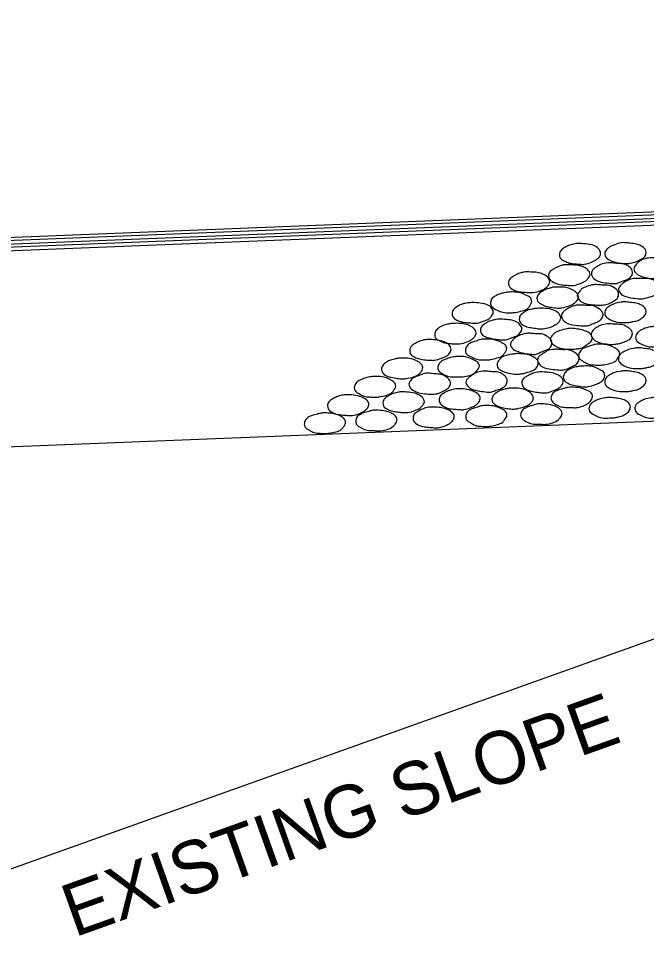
# Model space of a CAD drawing. Extents: x 714919 to 718439, y 1619644 to 1621844.
# Drawn here: x 716119 to 716262.2, y 1620757.6 to 1620966.5 of the extents above; entities that cross this region are included whole.
import ezdxf

# ---------------------------------------------------------------- set-up
doc = ezdxf.new("R2010")
doc.units = 0
doc.layers.add('R_Annotation', color=7, linetype='Continuous')
doc.layers.add('R_Draft', color=7, linetype='Continuous')

msp = doc.modelspace()

# ---------------------------------------------------------------- linework, layer by layer
at = {"layer": 'R_Draft'}
for p, q in [((716083.88, 1620915.32), (717366.08, 1620966.55)), ((716079.01, 1620912.92), (717370.38, 1620964.41)), ((716080.68, 1620913.71), (717368.96, 1620965.14)), ((716082.38, 1620914.6), (717367.45, 1620965.87)), ((716077.33, 1620912.05), (717371.84, 1620963.68)), ((715980.19, 1620863.5), (716482.51, 1620883.51)), ((716371.46, 1620863.61), (716076.17, 1620758.09))]:
    msp.add_line(p, q, dxfattribs=at)
for points in [[(716247.01, 1620915.27), (716248.65, 1620915.12), (716250.6, 1620914.57), (716251.52, 1620913.6), (716251.69, 1620913.07), (716251.23, 1620912.03), (716250.75, 1620911.63), (716249.63, 1620911.05), (716248.01, 1620910.53), (716247.16, 1620910.53), (716245.89, 1620910.64), (716244.55, 1620910.82), (716243.47, 1620911.26), (716242.43, 1620912.08), (716242.3, 1620912.76), (716242.59, 1620913.62), (716243.36, 1620914.28), (716244.13, 1620914.68), (716245.23, 1620915.07), (716245.89, 1620915.2), (716247.01, 1620915.27)], [(716257.38, 1620910.71), (716255.71, 1620910.83), (716253.81, 1620911.48), (716252.74, 1620912.37), (716252.62, 1620913), (716253.13, 1620913.97), (716253.69, 1620914.46), (716254.84, 1620914.93), (716256.39, 1620915.45), (716257.17, 1620915.45), (716258.46, 1620915.32), (716259.87, 1620915.12), (716260.89, 1620914.75), (716261.89, 1620913.88), (716262.07, 1620913.28), (716261.78, 1620912.34), (716261.02, 1620911.76), (716260.26, 1620911.35), (716259.14, 1620910.92), (716258.46, 1620910.77), (716257.38, 1620910.71)], [(716244.47, 1620910.43), (716246.12, 1620910.32), (716248.19, 1620909.72), (716249.13, 1620908.78), (716249.29, 1620908.21), (716248.73, 1620907.19), (716248.31, 1620906.76), (716247.09, 1620906.19), (716245.59, 1620905.72), (716244.7, 1620905.72), (716243.44, 1620905.79), (716242.06, 1620905.98), (716241.03, 1620906.4), (716239.97, 1620907.28), (716239.83, 1620907.91), (716240.14, 1620908.83), (716240.9, 1620909.41), (716241.66, 1620909.83), (716242.74, 1620910.25), (716243.44, 1620910.4), (716244.47, 1620910.43)], [(716254.27, 1620906.14), (716252.64, 1620906.34), (716250.7, 1620906.89), (716249.76, 1620907.81), (716249.58, 1620908.39), (716250.02, 1620909.38), (716250.63, 1620909.86), (716251.69, 1620910.45), (716253.32, 1620910.87), (716254.1, 1620910.87), (716255.39, 1620910.74), (716256.8, 1620910.64), (716257.87, 1620910.22), (716258.8, 1620909.31), (716258.97, 1620908.73), (716258.66, 1620907.79), (716257.96, 1620907.19), (716257.14, 1620906.86), (716256.04, 1620906.43), (716255.39, 1620906.19), (716254.27, 1620906.14)], [(716264.01, 1620907.28), (716262.35, 1620907.42), (716260.37, 1620908.07), (716259.44, 1620908.91), (716259.26, 1620909.51), (716259.81, 1620910.5), (716260.32, 1620911.05), (716261.39, 1620911.68), (716263.01, 1620911.98), (716263.77, 1620911.98), (716265.02, 1620912.03), (716266.44, 1620911.81), (716267.56, 1620911.32), (716268.54, 1620910.45), (716268.7, 1620909.9), (716268.38, 1620908.86), (716267.64, 1620908.29), (716266.86, 1620907.97), (716265.76, 1620907.58), (716265.02, 1620907.36), (716264.01, 1620907.28)], [(716235.35, 1620908.78), (716237, 1620908.7), (716239.02, 1620908.07), (716239.96, 1620907.11), (716240.1, 1620906.56), (716239.62, 1620905.54), (716239.08, 1620905.06), (716237.92, 1620904.49), (716236.35, 1620904.09), (716235.54, 1620904.09), (716234.28, 1620904.19), (716232.87, 1620904.33), (716231.85, 1620904.72), (716230.83, 1620905.63), (716230.7, 1620906.24), (716231.01, 1620907.16), (716231.74, 1620907.76), (716232.5, 1620908.17), (716233.55, 1620908.6), (716234.28, 1620908.76), (716235.35, 1620908.78)], [(716251.2, 1620901.24), (716249.49, 1620901.34), (716247.5, 1620901.89), (716246.54, 1620902.89), (716246.38, 1620903.43), (716246.98, 1620904.4), (716247.4, 1620904.91), (716248.53, 1620905.46), (716250.08, 1620905.88), (716251.02, 1620905.88), (716252.25, 1620905.79), (716253.61, 1620905.69), (716254.66, 1620905.29), (716255.63, 1620904.35), (716255.8, 1620903.77), (716255.52, 1620902.84), (716254.79, 1620902.24), (716254.03, 1620901.78), (716252.85, 1620901.39), (716252.25, 1620901.27), (716251.2, 1620901.24)], [(716260.71, 1620902.63), (716259, 1620902.84), (716256.99, 1620903.36), (716255.94, 1620904.3), (716255.8, 1620904.85), (716256.39, 1620905.84), (716256.91, 1620906.31), (716258.16, 1620907), (716259.68, 1620907.32), (716260.47, 1620907.32), (716261.73, 1620907.29), (716263.12, 1620907.16), (716264.19, 1620906.69), (716265.08, 1620905.77), (716265.24, 1620905.19), (716264.94, 1620904.3), (716264.22, 1620903.67), (716263.5, 1620903.28), (716262.44, 1620902.96), (716261.78, 1620902.78), (716260.71, 1620902.63)], [(716231.22, 1620904.23), (716232.87, 1620904.12), (716234.83, 1620903.43), (716235.88, 1620902.6), (716235.99, 1620902.07), (716235.48, 1620900.95), (716234.98, 1620900.38), (716233.83, 1620899.92), (716232.29, 1620899.58), (716231.43, 1620899.48), (716230.19, 1620899.51), (716228.73, 1620899.8), (716227.76, 1620900.27), (716226.73, 1620901.05), (716226.58, 1620901.66), (716226.85, 1620902.6), (716227.62, 1620903.25), (716228.36, 1620903.62), (716229.48, 1620903.99), (716230.17, 1620904.12), (716231.22, 1620904.23)], [(716241.92, 1620905.32), (716243.6, 1620905.29), (716245.57, 1620904.53), (716246.48, 1620903.73), (716246.66, 1620903.09), (716246.12, 1620902.03), (716245.62, 1620901.6), (716244.54, 1620901.08), (716242.89, 1620900.63), (716242.09, 1620900.53), (716240.83, 1620900.69), (716239.49, 1620900.9), (716238.39, 1620901.34), (716237.34, 1620902.12), (716237.19, 1620902.78), (716237.5, 1620903.67), (716238.31, 1620904.32), (716239.04, 1620904.75), (716240.14, 1620905.09), (716240.83, 1620905.29), (716241.92, 1620905.32)], [(716222.54, 1620901.81), (716224.22, 1620901.69), (716226.14, 1620901.14), (716227.11, 1620900.19), (716227.23, 1620899.61), (716226.76, 1620898.61), (716226.27, 1620898.14), (716225.14, 1620897.65), (716223.54, 1620897.12), (716222.71, 1620897.12), (716221.47, 1620897.23), (716220.09, 1620897.41), (716219.01, 1620897.75), (716217.97, 1620898.69), (716217.84, 1620899.28), (716218.15, 1620900.22), (716218.9, 1620900.81), (716219.67, 1620901.27), (716220.79, 1620901.63), (716221.47, 1620901.74), (716222.54, 1620901.81)], [(716257.32, 1620897.29), (716255.63, 1620897.33), (716253.81, 1620897.97), (716252.74, 1620898.88), (716252.62, 1620899.4), (716253.06, 1620900.51), (716253.69, 1620900.98), (716254.76, 1620901.52), (716256.39, 1620901.89), (716257.17, 1620901.97), (716258.45, 1620901.86), (716259.82, 1620901.65), (716260.89, 1620901.27), (716261.89, 1620900.42), (716262.07, 1620899.85), (716261.78, 1620898.91), (716261.02, 1620898.23), (716260.26, 1620897.76), (716259.11, 1620897.49), (716258.38, 1620897.33), (716257.32, 1620897.29)], [(716237.82, 1620900.51), (716239.54, 1620900.45), (716241.45, 1620899.85), (716242.43, 1620898.96), (716242.59, 1620898.38), (716242.11, 1620897.29), (716241.56, 1620896.86), (716240.49, 1620896.31), (716238.83, 1620895.89), (716238.02, 1620895.81), (716236.82, 1620895.95), (716235.46, 1620896.16), (716234.34, 1620896.53), (716233.29, 1620897.39), (716233.16, 1620897.97), (716233.44, 1620898.91), (716234.22, 1620899.58), (716234.94, 1620900.03), (716236.06, 1620900.32), (716236.85, 1620900.45), (716237.82, 1620900.51)], [(716247.61, 1620896.49), (716245.88, 1620896.66), (716243.94, 1620897.2), (716242.92, 1620898.17), (716242.76, 1620898.73), (716243.29, 1620899.8), (716243.84, 1620900.22), (716244.96, 1620900.81), (716246.57, 1620901.24), (716247.37, 1620901.24), (716248.61, 1620901.14), (716249.99, 1620901.05), (716251.14, 1620900.51), (716252.07, 1620899.71), (716252.25, 1620899.04), (716251.91, 1620898.1), (716251.2, 1620897.54), (716250.39, 1620897.17), (716249.36, 1620896.76), (716248.61, 1620896.52), (716247.61, 1620896.49)], [(716228.93, 1620898.02), (716230.64, 1620897.91), (716232.63, 1620897.36), (716233.58, 1620896.37), (716233.76, 1620895.82), (716233.23, 1620894.8), (716232.74, 1620894.33), (716231.56, 1620893.83), (716229.99, 1620893.33), (716229.2, 1620893.33), (716227.92, 1620893.44), (716226.53, 1620893.7), (716225.51, 1620893.98), (716224.44, 1620894.88), (716224.3, 1620895.52), (716224.61, 1620896.4), (716225.4, 1620897.02), (716226.14, 1620897.47), (716227.21, 1620897.81), (716227.92, 1620897.99), (716228.93, 1620898.02)], [(716218.59, 1620897.08), (716220.27, 1620897.02), (716222.23, 1620896.36), (716223.17, 1620895.48), (716223.33, 1620894.95), (716222.84, 1620893.85), (716222.31, 1620893.4), (716221.23, 1620892.85), (716219.61, 1620892.44), (716218.75, 1620892.39), (716217.54, 1620892.46), (716216.19, 1620892.67), (716215.08, 1620893.09), (716214.03, 1620893.88), (716213.88, 1620894.54), (716214.17, 1620895.42), (716215, 1620896.15), (716215.69, 1620896.53), (716216.83, 1620896.89), (716217.57, 1620897.02), (716218.59, 1620897.08)], [(716245.02, 1620891.21), (716243.37, 1620891.24), (716241.37, 1620891.94), (716240.39, 1620892.86), (716240.23, 1620893.44), (716240.8, 1620894.48), (716241.32, 1620894.95), (716242.43, 1620895.42), (716244.07, 1620895.85), (716244.88, 1620895.95), (716246.12, 1620895.82), (716247.46, 1620895.58), (716248.53, 1620895.19), (716249.58, 1620894.4), (716249.76, 1620893.78), (716249.41, 1620892.83), (716248.61, 1620892.28), (716247.9, 1620891.73), (716246.85, 1620891.37), (716246.11, 1620891.24), (716245.02, 1620891.21)], [(716254.19, 1620892.26), (716252.61, 1620892.43), (716250.67, 1620892.99), (716249.73, 1620893.87), (716249.55, 1620894.46), (716249.94, 1620895.42), (716250.54, 1620896), (716251.57, 1620896.57), (716253.26, 1620896.94), (716254.06, 1620896.94), (716255.37, 1620896.89), (716256.75, 1620896.73), (716257.8, 1620896.24), (716258.77, 1620895.37), (716258.93, 1620894.74), (716258.64, 1620893.85), (716257.93, 1620893.22), (716257.11, 1620892.86), (716255.97, 1620892.52), (716255.34, 1620892.38), (716254.19, 1620892.26)], [(716264.35, 1620891.73), (716262.67, 1620891.76), (716260.84, 1620892.41), (716259.77, 1620893.32), (716259.66, 1620893.83), (716260.1, 1620894.95), (716260.73, 1620895.42), (716261.8, 1620895.95), (716263.43, 1620896.32), (716264.21, 1620896.41), (716265.49, 1620896.29), (716266.86, 1620896.08), (716267.93, 1620895.71), (716268.93, 1620894.85), (716269.11, 1620894.29), (716268.82, 1620893.35), (716268.06, 1620892.67), (716267.3, 1620892.2), (716266.15, 1620891.92), (716265.42, 1620891.76), (716264.35, 1620891.73)], [(716212.81, 1620893.4), (716214.46, 1620893.28), (716216.5, 1620892.64), (716217.49, 1620891.7), (716217.63, 1620891.16), (716217.08, 1620890.08), (716216.63, 1620889.69), (716215.4, 1620889.17), (716213.86, 1620888.67), (716213.04, 1620888.67), (716211.76, 1620888.74), (716210.4, 1620888.98), (716209.35, 1620889.37), (716208.33, 1620890.18), (716208.19, 1620890.89), (716208.48, 1620891.76), (716209.24, 1620892.41), (716210, 1620892.77), (716211.07, 1620893.19), (716211.76, 1620893.36), (716212.81, 1620893.4)], [(716225.54, 1620893.51), (716227.19, 1620893.4), (716229.2, 1620892.67), (716230.17, 1620891.88), (716230.3, 1620891.33), (716229.75, 1620890.21), (716229.35, 1620889.72), (716228.13, 1620889.19), (716226.61, 1620888.82), (716225.71, 1620888.74), (716224.48, 1620888.77), (716223.04, 1620889.04), (716222.05, 1620889.56), (716221.01, 1620890.29), (716220.9, 1620890.99), (716221.19, 1620891.88), (716221.9, 1620892.52), (716222.7, 1620892.86), (716223.8, 1620893.22), (716224.44, 1620893.4), (716225.54, 1620893.51)], [(716236.03, 1620890.05), (716234.39, 1620890.23), (716232.39, 1620890.84), (716231.3, 1620891.73), (716231.16, 1620892.36), (716231.69, 1620893.33), (716232.26, 1620893.83), (716233.41, 1620894.43), (716234.94, 1620894.8), (716235.82, 1620894.8), (716237.05, 1620894.69), (716238.49, 1620894.61), (716239.51, 1620894.08), (716240.46, 1620893.25), (716240.61, 1620892.59), (716240.3, 1620891.67), (716239.59, 1620891.12), (716238.86, 1620890.81), (716237.73, 1620890.39), (716237.08, 1620890.06), (716236.03, 1620890.05)], [(716251.3, 1620892.34), (716252.9, 1620892.23), (716254.99, 1620891.45), (716255.91, 1620890.69), (716256.05, 1620890.08), (716255.52, 1620889.04), (716255.13, 1620888.49), (716253.93, 1620887.98), (716252.4, 1620887.65), (716251.46, 1620887.57), (716250.23, 1620887.6), (716248.79, 1620887.82), (716247.82, 1620888.35), (716246.82, 1620889.13), (716246.66, 1620889.77), (716247.01, 1620890.69), (716247.67, 1620891.33), (716248.45, 1620891.65), (716249.6, 1620892.04), (716250.2, 1620892.23), (716251.3, 1620892.34)], [(716260.43, 1620886.82), (716258.74, 1620886.85), (716256.91, 1620887.5), (716255.85, 1620888.41), (716255.73, 1620888.92), (716256.17, 1620890.04), (716256.8, 1620890.51), (716257.87, 1620891.04), (716259.5, 1620891.42), (716260.28, 1620891.5), (716261.56, 1620891.38), (716262.93, 1620891.17), (716264, 1620890.8), (716265, 1620889.94), (716265.18, 1620889.38), (716264.89, 1620888.44), (716264.13, 1620887.76), (716263.37, 1620887.29), (716262.22, 1620887.02), (716261.49, 1620886.85), (716260.43, 1620886.82)], [(716206.46, 1620889.16), (716208.11, 1620889.11), (716210.05, 1620888.41), (716211.02, 1620887.54), (716211.16, 1620886.99), (716210.69, 1620885.91), (716210.16, 1620885.42), (716209.08, 1620884.9), (716207.46, 1620884.51), (716206.59, 1620884.43), (716205.36, 1620884.53), (716204, 1620884.79), (716202.91, 1620885.11), (716201.93, 1620885.97), (716201.76, 1620886.57), (716202.07, 1620887.48), (716202.8, 1620888.19), (716203.56, 1620888.59), (716204.71, 1620888.92), (716205.39, 1620889.11), (716206.46, 1620889.16)], [(716219.22, 1620889.56), (716220.93, 1620889.45), (716222.89, 1620888.72), (716223.89, 1620887.91), (716224.06, 1620887.41), (716223.47, 1620886.29), (716223.02, 1620885.78), (716221.79, 1620885.21), (716220.27, 1620884.9), (716219.48, 1620884.87), (716218.22, 1620884.87), (716216.78, 1620885.06), (716215.74, 1620885.58), (716214.74, 1620886.36), (716214.59, 1620887.04), (716214.93, 1620887.91), (716215.63, 1620888.59), (716216.42, 1620888.92), (716217.5, 1620889.3), (716218.18, 1620889.45), (716219.22, 1620889.56)], [(716232.87, 1620885.49), (716231.19, 1620885.62), (716229.2, 1620886.29), (716228.18, 1620887.1), (716228.1, 1620887.65), (716228.55, 1620888.72), (716229.09, 1620889.27), (716230.22, 1620889.79), (716231.79, 1620890.08), (716232.63, 1620890.18), (716233.88, 1620890.11), (716235.32, 1620889.93), (716236.29, 1620889.48), (716237.31, 1620888.66), (716237.48, 1620888.04), (716237.16, 1620887.1), (716236.4, 1620886.42), (716235.69, 1620886.12), (716234.59, 1620885.78), (716233.92, 1620885.62), (716232.87, 1620885.49)], [(716242.13, 1620886.46), (716240.46, 1620886.63), (716238.47, 1620887.17), (716237.47, 1620888.14), (716237.29, 1620888.67), (716237.81, 1620889.72), (716238.44, 1620890.11), (716239.51, 1620890.81), (716241.14, 1620891.16), (716241.98, 1620891.16), (716243.19, 1620891.08), (716244.55, 1620891.02), (716245.65, 1620890.5), (716246.61, 1620889.68), (716246.77, 1620888.98), (716246.43, 1620888.07), (716245.67, 1620887.46), (716244.96, 1620887.14), (716243.87, 1620886.63), (716243.16, 1620886.47), (716242.13, 1620886.46)], [(716247.9, 1620887.36), (716249.6, 1620887.3), (716251.43, 1620886.6), (716252.53, 1620885.78), (716252.62, 1620885.15), (716252.17, 1620884.09), (716251.54, 1620883.63), (716250.51, 1620883.12), (716248.84, 1620882.69), (716248.08, 1620882.59), (716246.85, 1620882.74), (716245.51, 1620882.99), (716244.34, 1620883.38), (716243.36, 1620884.18), (716243.19, 1620884.84), (716243.5, 1620885.71), (716244.23, 1620886.39), (716244.99, 1620886.81), (716246.12, 1620887.14), (716246.88, 1620887.3), (716247.9, 1620887.36)], [(716212.86, 1620880.96), (716211.2, 1620881.07), (716209.21, 1620881.68), (716208.15, 1620882.62), (716208.01, 1620883.2), (716208.53, 1620884.24), (716209.09, 1620884.69), (716210.31, 1620885.18), (716211.91, 1620885.7), (716212.7, 1620885.7), (716213.96, 1620885.58), (716215.34, 1620885.42), (716216.36, 1620884.98), (716217.28, 1620884.14), (716217.47, 1620883.5), (716217.15, 1620882.56), (716216.47, 1620881.99), (716215.77, 1620881.64), (716214.69, 1620881.13), (716213.9, 1620880.99), (716212.86, 1620880.96)], [(716225.85, 1620881.44), (716224.19, 1620881.65), (716222.23, 1620882.17), (716221.18, 1620883.11), (716221, 1620883.64), (716221.55, 1620884.69), (716222.1, 1620885.08), (716223.25, 1620885.79), (716224.82, 1620886.18), (716225.67, 1620886.18), (716226.89, 1620886.07), (716228.31, 1620885.97), (716229.39, 1620885.49), (716230.27, 1620884.61), (716230.43, 1620883.96), (716230.14, 1620883.08), (716229.44, 1620882.43), (716228.7, 1620882.12), (716227.57, 1620881.73), (716226.94, 1620881.49), (716225.85, 1620881.44)], [(716238.39, 1620886), (716240.01, 1620885.91), (716242.06, 1620885.28), (716243.02, 1620884.35), (716243.16, 1620883.74), (716242.66, 1620882.74), (716242.13, 1620882.3), (716240.99, 1620881.76), (716239.42, 1620881.26), (716238.57, 1620881.26), (716237.29, 1620881.39), (716235.93, 1620881.62), (716234.86, 1620881.96), (716233.91, 1620882.83), (716233.73, 1620883.48), (716234.04, 1620884.4), (716234.75, 1620884.95), (716235.54, 1620885.36), (716236.64, 1620885.83), (716237.29, 1620885.97), (716238.39, 1620886)], [(716257.32, 1620881.58), (716255.63, 1620881.62), (716253.81, 1620882.26), (716252.74, 1620883.17), (716252.62, 1620883.69), (716253.06, 1620884.8), (716253.69, 1620885.27), (716254.76, 1620885.81), (716256.39, 1620886.18), (716257.17, 1620886.26), (716258.45, 1620886.15), (716259.82, 1620885.94), (716260.89, 1620885.56), (716261.89, 1620884.71), (716262.07, 1620884.14), (716261.78, 1620883.2), (716261.02, 1620882.52), (716260.26, 1620882.05), (716259.11, 1620881.78), (716258.38, 1620881.62), (716257.32, 1620881.58)], [(716200.23, 1620884.95), (716201.89, 1620884.9), (716203.85, 1620884.21), (716204.84, 1620883.38), (716205.02, 1620882.86), (716204.47, 1620881.73), (716203.98, 1620881.18), (716202.8, 1620880.68), (716201.26, 1620880.33), (716200.45, 1620880.28), (716199.18, 1620880.31), (716197.72, 1620880.52), (716196.73, 1620881.02), (716195.75, 1620881.8), (716195.57, 1620882.43), (716195.89, 1620883.38), (716196.62, 1620884.03), (716197.4, 1620884.4), (716198.5, 1620884.76), (716199.14, 1620884.9), (716200.23, 1620884.95)], [(716206.73, 1620881.46), (716208.38, 1620881.36), (716210.4, 1620880.75), (716211.37, 1620879.81), (716211.54, 1620879.23), (716210.99, 1620878.24), (716210.52, 1620877.75), (716209.35, 1620877.24), (716207.77, 1620876.77), (716206.96, 1620876.77), (716205.68, 1620876.86), (716204.32, 1620877.06), (716203.27, 1620877.43), (716202.22, 1620878.3), (716202.1, 1620878.93), (716202.4, 1620879.84), (716203.17, 1620880.44), (716203.9, 1620880.88), (716205.02, 1620881.26), (716205.68, 1620881.44), (716206.73, 1620881.46)], [(716219.54, 1620882.17), (716221.23, 1620882.04), (716223.1, 1620881.44), (716224.15, 1620880.49), (716224.25, 1620879.89), (716223.73, 1620878.92), (716223.25, 1620878.46), (716222.13, 1620877.93), (716220.53, 1620877.43), (716219.72, 1620877.43), (716218.43, 1620877.54), (716217.08, 1620877.69), (716216.02, 1620878.13), (716215.03, 1620878.98), (716214.87, 1620879.63), (716215.16, 1620880.52), (716215.89, 1620881.12), (716216.68, 1620881.59), (716217.8, 1620881.96), (716218.43, 1620882.12), (716219.54, 1620882.17)], [(716231.64, 1620882.3), (716233.29, 1620882.25), (716235.25, 1620881.59), (716236.19, 1620880.7), (716236.35, 1620880.13), (716235.9, 1620879.03), (716235.38, 1620878.58), (716234.28, 1620878.08), (716232.63, 1620877.64), (716231.79, 1620877.54), (716230.58, 1620877.67), (716229.23, 1620877.91), (716228.13, 1620878.32), (716227.08, 1620879.13), (716226.94, 1620879.78), (716227.23, 1620880.65), (716228.04, 1620881.33), (716228.73, 1620881.76), (716229.85, 1620882.09), (716230.61, 1620882.25), (716231.64, 1620882.3)], [(716245.12, 1620882.56), (716246.8, 1620882.38), (716248.65, 1620881.8), (716249.73, 1620880.94), (716249.83, 1620880.36), (716249.37, 1620879.35), (716248.76, 1620878.8), (716247.67, 1620878.24), (716246.11, 1620877.88), (716245.26, 1620877.88), (716244.02, 1620877.91), (716242.66, 1620878.08), (716241.56, 1620878.55), (716240.54, 1620879.44), (716240.38, 1620880.07), (716240.69, 1620880.96), (716241.41, 1620881.62), (716242.19, 1620881.91), (716243.32, 1620882.27), (716244.07, 1620882.46), (716245.12, 1620882.56)], [(716194.15, 1620880.81), (716195.88, 1620880.68), (716197.72, 1620880.07), (716198.76, 1620879.16), (716198.89, 1620878.55), (716198.34, 1620877.54), (716197.85, 1620877.11), (716196.73, 1620876.57), (716195.13, 1620876.09), (716194.36, 1620876.09), (716193.06, 1620876.18), (716191.7, 1620876.35), (716190.62, 1620876.77), (716189.6, 1620877.64), (716189.47, 1620878.3), (716189.75, 1620879.18), (716190.51, 1620879.78), (716191.27, 1620880.21), (716192.4, 1620880.62), (716193.06, 1620880.75), (716194.15, 1620880.81)], [(716238.26, 1620878.77), (716239.86, 1620878.61), (716241.77, 1620878.01), (716242.76, 1620877.14), (716242.92, 1620876.57), (716242.45, 1620875.54), (716241.92, 1620875), (716240.82, 1620874.44), (716239.2, 1620874.08), (716238.39, 1620874.08), (716237.11, 1620874.11), (716235.75, 1620874.24), (716234.65, 1620874.76), (716233.62, 1620875.6), (716233.47, 1620876.26), (716233.79, 1620877.19), (716234.54, 1620877.79), (716235.32, 1620878.13), (716236.4, 1620878.46), (716237.16, 1620878.69), (716238.26, 1620878.77)], [(716253.72, 1620875.53), (716252.03, 1620875.56), (716250.21, 1620876.21), (716249.14, 1620877.11), (716249.02, 1620877.63), (716249.46, 1620878.75), (716250.09, 1620879.22), (716251.16, 1620879.75), (716252.79, 1620880.12), (716253.57, 1620880.2), (716254.85, 1620880.09), (716256.22, 1620879.88), (716257.29, 1620879.51), (716258.29, 1620878.65), (716258.47, 1620878.08), (716258.18, 1620877.15), (716257.42, 1620876.47), (716256.66, 1620876), (716255.51, 1620875.72), (716254.78, 1620875.56), (716253.72, 1620875.53)], [(716264.19, 1620875.53), (716262.51, 1620875.56), (716260.68, 1620876.21), (716259.61, 1620877.11), (716259.5, 1620877.63), (716259.93, 1620878.75), (716260.57, 1620879.22), (716261.63, 1620879.75), (716263.27, 1620880.12), (716264.04, 1620880.2), (716265.32, 1620880.09), (716266.7, 1620879.88), (716267.76, 1620879.51), (716268.77, 1620878.65), (716268.95, 1620878.08), (716268.65, 1620877.15), (716267.89, 1620876.47), (716267.13, 1620876), (716265.98, 1620875.72), (716265.26, 1620875.56), (716264.19, 1620875.53)], [(716188.79, 1620876.7), (716190.49, 1620876.57), (716192.5, 1620875.91), (716193.43, 1620875.07), (716193.58, 1620874.55), (716193.06, 1620873.43), (716192.61, 1620872.9), (716191.38, 1620872.35), (716189.86, 1620872.06), (716189.05, 1620871.99), (716187.82, 1620872.03), (716186.38, 1620872.19), (716185.33, 1620872.74), (716184.31, 1620873.51), (716184.16, 1620874.15), (716184.46, 1620875.07), (716185.2, 1620875.75), (716185.94, 1620876.09), (716187.08, 1620876.41), (716187.79, 1620876.57), (716188.79, 1620876.7)], [(716200.6, 1620877.33), (716202.25, 1620877.15), (716204.19, 1620876.54), (716205.16, 1620875.67), (716205.31, 1620875.12), (716204.87, 1620874.08), (716204.34, 1620873.58), (716203.24, 1620872.96), (716201.6, 1620872.62), (716200.76, 1620872.62), (716199.52, 1620872.66), (716198.16, 1620872.8), (716197.07, 1620873.34), (716196.01, 1620874.15), (716195.89, 1620874.81), (716196.15, 1620875.73), (716196.96, 1620876.33), (716197.66, 1620876.67), (716198.85, 1620876.99), (716199.56, 1620877.24), (716200.6, 1620877.33)], [(716213.64, 1620878.01), (716215.3, 1620877.88), (716217.18, 1620877.28), (716218.22, 1620876.35), (716218.35, 1620875.76), (716217.84, 1620874.76), (716217.34, 1620874.31), (716216.26, 1620873.76), (716214.66, 1620873.3), (716213.78, 1620873.3), (716212.52, 1620873.42), (716211.16, 1620873.58), (716210.1, 1620873.97), (716209.08, 1620874.84), (716208.96, 1620875.46), (716209.21, 1620876.38), (716209.97, 1620876.96), (716210.74, 1620877.4), (716211.89, 1620877.82), (716212.52, 1620877.96), (716213.64, 1620878.01)], [(716225.59, 1620878.35), (716227.23, 1620878.27), (716229.27, 1620877.54), (716230.2, 1620876.75), (716230.35, 1620876.18), (716229.78, 1620875.08), (716229.39, 1620874.57), (716228.17, 1620874.03), (716226.66, 1620873.66), (716225.75, 1620873.61), (716224.53, 1620873.63), (716223.09, 1620873.87), (716222.1, 1620874.4), (716221.08, 1620875.18), (716220.95, 1620875.83), (716221.23, 1620876.75), (716221.97, 1620877.4), (716222.75, 1620877.72), (716223.86, 1620878.09), (716224.51, 1620878.27), (716225.59, 1620878.35)]]:
    msp.add_spline(points, degree=3, dxfattribs=at)

# ---------------------------------------------------------------- texts
at = {"layer": 'R_Annotation'}
msp.add_text('EXISTING SLOPE', height=12, rotation=19.6609, dxfattribs=at).set_placement((716131.75, 1620757.17))

doc.saveas('drawing.dxf')
